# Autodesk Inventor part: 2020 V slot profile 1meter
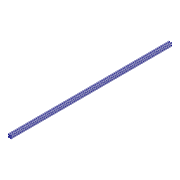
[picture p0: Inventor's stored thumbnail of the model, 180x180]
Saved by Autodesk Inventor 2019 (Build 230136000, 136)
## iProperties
Created: 2018-10
Part Number: 2020 V slot profile 1meter
Material: Aluminum 6061
Document SubType Name: Modeling
Designer: R&D Lab User 1
Density: 2.7 g/cm^3
Appearance: Aluminum - Flat
Author: R&D Lab User 1
Revision Number: ANY
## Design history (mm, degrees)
feature "Solid2"
sketch "Sketch1"
  geometry: L1 (-1.168, 13.9)-(-6.368, 13.9) reference; L2 (-7.368, 12.9)-(-7.368, 7.7) reference; L3 (-7.368, 7.7)-(-6.668, 7) reference; L4 (-6.668, 7)-(-6.068, 7) reference; L5 (-5.568, 7.5)-(-5.568, 8.9) reference; L6 (-5.068, 9.4)-(-4.136, 9.4) reference; L7 (-3.782, 9.254)-(-1.414, 6.886) reference; L8 (-1.268, 6.532)-(-1.268, 1.268) reference; L9 (-1.414, 0.914)-(-3.782, -1.454) reference; L10 (-4.136, -1.6)-(-5.068, -1.6) reference; L11 (-5.568, -1.1)-(-5.568, 0.3) reference; L12 (-6.068, 0.8)-(-6.668, 0.8) reference; L13 (-6.668, 0.8)-(-7.368, 0.1) reference; L14 (-7.368, 0.1)-(-7.368, -5.1) reference; L15 (-6.368, -6.1)-(-1.168, -6.1) reference; L16 (-1.168, -6.1)-(-0.468, -5.4) reference; L17 (-0.468, -5.4)-(-0.468, -4.801) reference; L18 (-0.968, -4.301)-(-2.368, -4.301) reference; L19 (-2.868, -3.801)-(-2.868, -2.868) reference; L20 (-2.721, -2.514)-(-0.354, -0.146) reference; L21 (0, 0)-(5.264, 0) reference; L22 (5.618, -0.146)-(7.986, -2.514) reference; L23 (8.132, -2.868)-(8.132, -3.801) reference; L24 (7.632, -4.301)-(6.232, -4.301) reference; L25 (5.732, -4.801)-(5.732, -5.4) reference; L26 (5.732, -5.4)-(6.432, -6.1) reference; L27 (6.432, -6.1)-(11.632, -6.1) reference; L28 (12.632, -5.1)-(12.632, 0.1) reference; L29 (12.632, 0.1)-(11.932, 0.8) reference; L30 (11.932, 0.8)-(11.333, 0.8) reference; L31 (10.833, 0.3)-(10.833, -1.1) reference; L32 (10.333, -1.6)-(9.4, -1.6) reference; L33 (9.046, -1.454)-(6.679, 0.914) reference; L34 (6.532, 1.268)-(6.532, 6.532) reference; L35 (6.679, 6.886)-(9.046, 9.254) reference; L36 (9.4, 9.4)-(10.333, 9.4) reference; L37 (10.833, 8.9)-(10.833, 7.5) reference; L38 (11.333, 7)-(11.932, 7) reference; L39 (11.932, 7)-(12.632, 7.7) reference; L40 (12.632, 7.7)-(12.632, 12.9) reference; L41 (11.632, 13.9)-(6.432, 13.9) reference; L42 (6.432, 13.9)-(5.732, 13.2) reference; L43 (5.732, 13.2)-(5.732, 12.601) reference; L44 (6.232, 12.101)-(7.632, 12.101) reference; L45 (8.132, 11.601)-(8.132, 10.668) reference; L46 (7.986, 10.314)-(5.618, 7.946) reference; L47 (5.264, 7.8)-(0, 7.8) reference; L48 (-0.354, 7.946)-(-2.721, 10.314) reference; L49 (-2.868, 10.668)-(-2.868, 11.601) reference; L50 (-2.368, 12.101)-(-0.968, 12.101) reference; L51 (-0.468, 12.601)-(-0.468, 13.2) reference; L52 (-0.468, 13.2)-(-1.168, 13.9) reference; C1 r 2.5 at (2.632, 3.9) reference; A1 r 1 centre (-6.368, 12.9) between (-6.368, 13.9) and (-7.368, 12.9) reference; A2 r 0.5 centre (-6.068, 7.5) between (-6.068, 7) and (-5.568, 7.5) reference; A3 r 0.5 centre (-5.068, 8.9) between (-5.068, 9.4) and (-5.568, 8.9) reference; A4 r 0.5 centre (-4.136, 8.9) between (-3.782, 9.254) and (-4.136, 9.4) reference; A5 r 0.5 centre (-1.768, 6.532) between (-1.268, 6.532) and (-1.414, 6.886) reference; A6 r 0.5 centre (-1.768, 1.268) between (-1.414, 0.914) and (-1.268, 1.268) reference; A7 r 0.5 centre (-4.136, -1.1) between (-4.136, -1.6) and (-3.782, -1.454) reference; A8 r 0.5 centre (-5.068, -1.1) between (-5.568, -1.1) and (-5.068, -1.6) reference; A9 r 0.5 centre (-6.068, 0.3) between (-5.568, 0.3) and (-6.068, 0.8) reference; A10 r 1 centre (-6.368, -5.1) between (-7.368, -5.1) and (-6.368, -6.1) reference; A11 r 0.5 centre (-0.968, -4.801) between (-0.468, -4.801) and (-0.968, -4.301) reference; A12 r 0.5 centre (-2.368, -3.801) between (-2.868, -3.801) and (-2.368, -4.301) reference; A13 r 0.5 centre (-2.368, -2.868) between (-2.721, -2.514) and (-2.868, -2.868) reference; A14 r 0.5 centre (0, -0.5) between (0, 0) and (-0.354, -0.146) reference; A15 r 0.5 centre (5.264, -0.5) between (5.618, -0.146) and (5.264, 0) reference; A16 r 0.5 centre (7.632, -2.868) between (8.132, -2.868) and (7.986, -2.514) reference; A17 r 0.5 centre (7.632, -3.801) between (7.632, -4.301) and (8.132, -3.801) reference; A18 r 0.5 centre (6.232, -4.801) between (6.232, -4.301) and (5.732, -4.801) reference; A19 r 1 centre (11.632, -5.1) between (11.632, -6.1) and (12.632, -5.1) reference; A20 r 0.5 centre (11.333, 0.3) between (11.333, 0.8) and (10.833, 0.3) reference; A21 r 0.5 centre (10.333, -1.1) between (10.333, -1.6) and (10.833, -1.1) reference; A22 r 0.5 centre (9.4, -1.1) between (9.046, -1.454) and (9.4, -1.6) reference; A23 r 0.5 centre (7.032, 1.268) between (6.532, 1.268) and (6.679, 0.914) reference; A24 r 0.5 centre (7.032, 6.532) between (6.679, 6.886) and (6.532, 6.532) reference; A25 r 0.5 centre (9.4, 8.9) between (9.4, 9.4) and (9.046, 9.254) reference; A26 r 0.5 centre (10.333, 8.9) between (10.833, 8.9) and (10.333, 9.4) reference; A27 r 0.5 centre (11.333, 7.5) between (10.833, 7.5) and (11.333, 7) reference; A28 r 1 centre (11.632, 12.9) between (12.632, 12.9) and (11.632, 13.9) reference; A29 r 0.5 centre (6.232, 12.601) between (5.732, 12.601) and (6.232, 12.101) reference; A30 r 0.5 centre (7.632, 11.601) between (8.132, 11.601) and (7.632, 12.101) reference; A31 r 0.5 centre (7.632, 10.668) between (7.986, 10.314) and (8.132, 10.668) reference; A32 r 0.5 centre (5.264, 8.3) between (5.264, 7.8) and (5.618, 7.946) reference; A33 r 0.5 centre (0, 8.3) between (-0.354, 7.946) and (0, 7.8) reference; A34 r 0.5 centre (-2.368, 10.668) between (-2.868, 10.668) and (-2.721, 10.314) reference; A35 r 0.5 centre (-2.368, 11.601) between (-2.368, 12.101) and (-2.868, 11.601) reference; A36 r 0.5 centre (-0.968, 12.601) between (-0.968, 12.101) and (-0.468, 12.601) reference; 1 further point
extrude "Extrusion1" join sketch "Sketch1" distance "d0" = 611.2; taper "d1" = 0 deg
body "Solid1"
node "Projected Loop1"
